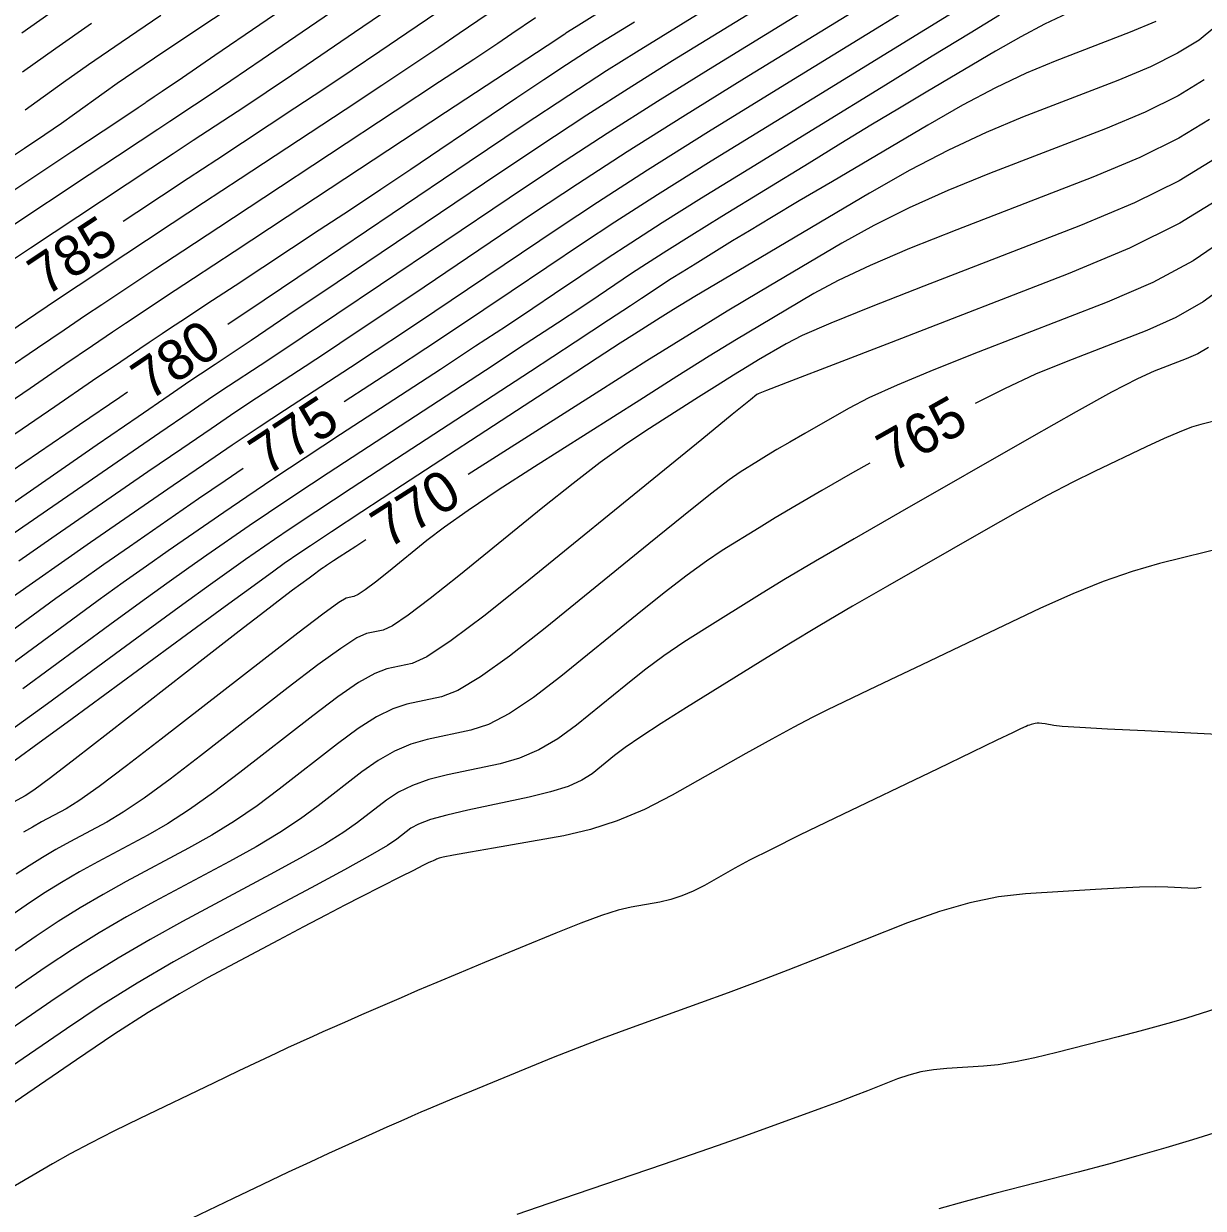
# Model space of a CAD drawing. Extents: x 2079879 to 2092887, y 778083 to 784051.
# Drawn here: x 2084644.1 to 2084725.9, y 781224.5 to 781306.6 of the extents above; entities that cross this region are included whole.
import ezdxf

# ---------------------------------------------------------------- set-up
doc = ezdxf.new("R2010")
doc.units = 0
doc.layers.add('DT_X_Contour_Major', color=7, linetype='Continuous')
doc.layers.add('DT_X_Contour_Minor', color=7, linetype='Continuous')

msp = doc.modelspace()

# ---------------------------------------------------------------- linework, layer by layer
at = {"layer": 'DT_X_Contour_Major'}
for points in [[(2084741.676, 781340.837), (2084739.539, 781339.138), (2084738.784, 781338.575), (2084737.437, 781337.615), (2084735.497, 781336.257), (2084732.963, 781334.501), (2084725.417, 781329.289), (2084722.475, 781327.287), (2084719.307, 781325.187), (2084715.915, 781322.99), (2084712.298, 781320.696), (2084702.351, 781314.45), (2084698.865, 781312.264), (2084695.864, 781310.388), (2084693.35, 781308.824), (2084691.322, 781307.571), (2084686.561, 781304.644), (2084684.498, 781303.346), (2084681.879, 781301.647), (2084678.705, 781299.547), (2084674.974, 781297.045), (2084664.286, 781289.839), (2084660.748, 781287.454), (2084658.242, 781285.766)], [(2084675.583, 781309.33), (2084670.653, 781305.96), (2084668.781, 781304.687), (2084666.863, 781303.395), (2084664.9, 781302.085), (2084662.89, 781300.756), (2084657.47, 781297.188), (2084655.498, 781295.889), (2084653.65, 781294.67), (2084651.925, 781293.53), (2084650.987, 781292.91)], [(2084709.118, 781307.766), (2084696.219, 781299.836), (2084691.754, 781297.078), (2084688.035, 781294.75), (2084685.06, 781292.852), (2084682.83, 781291.384), (2084677.876, 781288.044), (2084675.982, 781286.773), (2084674.013, 781285.463), (2084671.97, 781284.114), (2084669.854, 781282.726), (2084666.313, 781280.413)], [(2084653.584, 781307.181), (2084650.834, 781305.317), (2084648.586, 781303.768), (2084646.839, 781302.533), (2084644.183, 781300.621)], [(2084725.928, 781302.728), (2084724.124, 781301.616), (2084721.839, 781300.483), (2084719.073, 781299.33), (2084711.053, 781296.227), (2084708.156, 781295.053), (2084705.481, 781293.856), (2084703.028, 781292.636), (2084700.797, 781291.395), (2084695.143, 781288.054), (2084692.857, 781286.684), (2084690.242, 781285.08), (2084687.297, 781283.243), (2084684.022, 781281.171), (2084674.895, 781275.365)], [(2084727.617, 781288.617), (2084725.858, 781287.34), (2084723.966, 781286.25), (2084721.939, 781285.347), (2084716.357, 781283.187), (2084714.24, 781282.315), (2084712.077, 781281.32), (2084710.05, 781280.293)], [(2084651.276, 781281.073), (2084650.759, 781280.72), (2084647.95, 781278.804), (2084636.571, 781271.044)], [(2084659.302, 781275.786), (2084658.05, 781274.942), (2084656.208, 781273.68), (2084651.413, 781270.372), (2084649.647, 781269.145), (2084647.946, 781267.945), (2084646.308, 781266.773), (2084644.734, 781265.629), (2084640.624, 781262.613)], [(2084702.735, 781276.167), (2084701.539, 781275.482), (2084699.426, 781274.267), (2084697.643, 781273.229), (2084696.191, 781272.369), (2084695.069, 781271.685), (2084692.516, 781270.1), (2084691.43, 781269.378), (2084690.086, 781268.4), (2084688.484, 781267.166), (2084686.625, 781265.677), (2084681.322, 781261.365), (2084679.44, 781259.92), (2084677.773, 781258.818), (2084676.32, 781258.061), (2084675.081, 781257.649), (2084672.062, 781257.006), (2084670.93, 781256.685), (2084669.798, 781256.204), (2084668.665, 781255.562), (2084667.533, 781254.76), (2084664.512, 781252.406), (2084663.277, 781251.504), (2084661.838, 781250.562), (2084660.195, 781249.58), (2084658.347, 781248.559), (2084653.147, 781245.783), (2084651.216, 781244.719), (2084649.324, 781243.608), (2084647.47, 781242.451), (2084645.655, 781241.247), (2084640.867, 781237.976)], [(2084667.812, 781270.85), (2084667.107, 781270.395), (2084665.958, 781269.645), (2084665.574, 781269.394), (2084665.284, 781269.203), (2084665.088, 781269.074), (2084664.986, 781269.006), (2084664.839, 781268.904), (2084664.737, 781268.832), (2084664.541, 781268.689), (2084664.251, 781268.478), (2084663.867, 781268.196), (2084662.719, 781267.354), (2084662.022, 781266.828), (2084660.795, 781265.884), (2084659.036, 781264.521), (2084656.745, 781262.739), (2084649.929, 781257.428), (2084647.654, 781255.664), (2084645.94, 781254.357), (2084644.789, 781253.507), (2084644.198, 781253.114), (2084643.373, 781252.673)], [(2084725.724, 781246.75), (2084725.254, 781246.69), (2084723.402, 781246.781), (2084722.567, 781246.797), (2084721.452, 781246.776), (2084720.057, 781246.718), (2084718.381, 781246.623), (2084713.538, 781246.322), (2084711.665, 781246.111), (2084709.677, 781245.703), (2084707.575, 781245.1), (2084705.358, 781244.3), (2084699.294, 781241.905), (2084697.071, 781241.035), (2084694.949, 781240.22), (2084692.928, 781239.461), (2084691.008, 781238.757), (2084686.023, 781236.954), (2084684.196, 781236.284), (2084682.454, 781235.624), (2084680.796, 781234.976), (2084679.224, 781234.338), (2084675.143, 781232.652), (2084673.774, 781232.086), (2084672.73, 781231.652), (2084672.009, 781231.351), (2084671.612, 781231.183), (2084670.986, 781230.909), (2084670.638, 781230.756), (2084670.065, 781230.499), (2084669.267, 781230.14), (2084668.243, 781229.679), (2084665.213, 781228.311), (2084663.948, 781227.732), (2084662.426, 781227.021), (2084660.645, 781226.178), (2084658.607, 781225.204), (2084652.829, 781222.428)]]:
    msp.add_lwpolyline(points, dxfattribs=at)
at = {"layer": 'DT_X_Contour_Minor'}
for points in [[(2084669.907, 781312.997), (2084660.461, 781306.54), (2084657.347, 781304.412), (2084655.09, 781302.869), (2084653.688, 781301.912), (2084653.143, 781301.542), (2084652.832, 781301.334), (2084652.724, 781301.261), (2084652.632, 781301.199), (2084652.557, 781301.147), (2084652.499, 781301.106), (2084652.366, 781301.01), (2084652.024, 781300.782), (2084651.1, 781300.168), (2084649.593, 781299.169), (2084647.504, 781297.784), (2084641.154, 781293.578)], [(2084671.595, 781311.636), (2084663.383, 781306.022), (2084660.608, 781304.127), (2084658.441, 781302.652), (2084656.883, 781301.596), (2084655.933, 781300.961), (2084654.211, 781299.828), (2084653.378, 781299.279), (2084652.171, 781298.481), (2084650.59, 781297.435), (2084648.635, 781296.14), (2084642.923, 781292.356)], [(2084710.86, 781310.986), (2084696.559, 781302.195), (2084691.573, 781299.112), (2084687.34, 781296.457), (2084683.859, 781294.229), (2084681.131, 781292.43), (2084674.859, 781288.202), (2084672.587, 781286.675), (2084670.476, 781285.265), (2084668.524, 781283.971), (2084666.733, 781282.795), (2084662.168, 781279.813), (2084660.402, 781278.65), (2084658.528, 781277.396), (2084656.544, 781276.051), (2084654.452, 781274.615), (2084648.728, 781270.665), (2084646.702, 781269.261), (2084644.918, 781268.01), (2084643.374, 781266.913)], [(2084673.589, 781310.483), (2084667.018, 781305.991), (2084664.694, 781304.407), (2084662.652, 781303.023), (2084660.891, 781301.841), (2084659.411, 781300.859), (2084655.84, 781298.508), (2084654.438, 781297.584), (2084652.911, 781296.576), (2084651.257, 781295.482), (2084649.479, 781294.305), (2084644.567, 781291.051), (2084642.755, 781289.847)], [(2084705.975, 781310.132), (2084694.06, 781302.807), (2084689.794, 781300.164), (2084685.934, 781297.727), (2084682.48, 781295.498), (2084679.431, 781293.476), (2084671.842, 781288.359), (2084669.193, 781286.577), (2084666.939, 781285.067), (2084665.078, 781283.829), (2084663.611, 781282.863), (2084660.226, 781280.652), (2084658.803, 781279.711), (2084657.074, 781278.547), (2084655.039, 781277.16), (2084652.697, 781275.55), (2084646.043, 781270.959), (2084643.757, 781269.377)], [(2084701.091, 781309.278), (2084691.56, 781303.419), (2084688.016, 781301.216), (2084684.529, 781298.998), (2084681.102, 781296.767), (2084677.732, 781294.522), (2084668.825, 781288.517), (2084665.799, 781286.479), (2084663.401, 781284.868), (2084661.632, 781283.686), (2084660.49, 781282.932), (2084658.283, 781281.49), (2084657.204, 781280.772), (2084655.62, 781279.698), (2084653.533, 781278.269), (2084650.941, 781276.485), (2084643.358, 781271.252)], [(2084696.206, 781308.425), (2084689.061, 781304.032), (2084686.237, 781302.267), (2084683.124, 781300.269), (2084679.723, 781298.035), (2084676.033, 781295.567), (2084665.808, 781288.674), (2084662.405, 781286.381), (2084659.864, 781284.67), (2084658.185, 781283.544), (2084657.369, 781283), (2084656.341, 781282.329), (2084655.605, 781281.833), (2084654.167, 781280.85), (2084652.027, 781279.379), (2084649.186, 781277.42), (2084640.673, 781271.546)], [(2084659.657, 781308.566), (2084654.833, 781305.347), (2084653.154, 781304.221), (2084651.733, 781303.258), (2084650.572, 781302.458), (2084649.669, 781301.82), (2084647.608, 781300.335), (2084646.708, 781299.7), (2084645.554, 781298.909), (2084644.147, 781297.96), (2084642.487, 781296.854)], [(2084684.427, 781307.669), (2084682.38, 781306.384), (2084681.682, 781305.945), (2084681.596, 781305.892), (2084681.58, 781305.882), (2084681.569, 781305.875), (2084681.564, 781305.872), (2084681.557, 781305.867), (2084681.041, 781305.527), (2084673.326, 781300.448), (2084662.358, 781293.228), (2084658.679, 781290.805), (2084655.868, 781288.954), (2084653.926, 781287.674), (2084652.852, 781286.965), (2084651.147, 781285.835), (2084650.253, 781285.237), (2084648.852, 781284.289), (2084646.943, 781282.991), (2084644.525, 781281.344), (2084637.402, 781276.486)], [(2084677.576, 781308.177), (2084674.288, 781305.929), (2084672.868, 781304.967), (2084671.075, 781303.767), (2084668.908, 781302.329), (2084666.369, 781300.654), (2084659.099, 781295.868), (2084656.558, 781294.195), (2084654.389, 781292.765), (2084652.592, 781291.578), (2084651.165, 781290.635), (2084647.857, 781288.443), (2084646.504, 781287.542), (2084644.927, 781286.482), (2084643.126, 781285.262)], [(2084646.452, 781307.711), (2084643.969, 781305.958)], [(2084686.437, 781306.717), (2084684.062, 781305.257), (2084683.032, 781304.609), (2084681.725, 781303.761), (2084680.141, 781302.713), (2084678.28, 781301.465), (2084672.946, 781297.869), (2084670.923, 781296.509), (2084668.853, 781295.127), (2084666.737, 781293.722), (2084664.574, 781292.294), (2084658.745, 781288.457), (2084656.79, 781287.17), (2084655.297, 781286.186), (2084654.265, 781285.506), (2084653.696, 781285.13), (2084652.792, 781284.531), (2084652.128, 781284.084), (2084650.814, 781283.192), (2084648.851, 781281.856), (2084646.238, 781280.074), (2084638.403, 781274.731)], [(2084711.742, 781307.2), (2084709.71, 781305.967), (2084707.07, 781304.355), (2084703.824, 781302.362), (2084694.356, 781296.542), (2084691.079, 781294.517), (2084688.349, 781292.808), (2084686.166, 781291.415), (2084684.529, 781290.338), (2084680.893, 781287.887), (2084679.376, 781286.871), (2084677.55, 781285.661), (2084675.417, 781284.256), (2084672.975, 781282.658), (2084666.053, 781278.136), (2084663.601, 781276.528), (2084661.435, 781275.093), (2084659.556, 781273.832), (2084657.963, 781272.745), (2084654.098, 781270.078), (2084652.593, 781269.029), (2084650.974, 781267.881), (2084649.242, 781266.634), (2084647.397, 781265.288), (2084642.327, 781261.569)], [(2084679.57, 781307.024), (2084677.923, 781305.898), (2084676.954, 781305.247), (2084675.286, 781304.139), (2084672.917, 781302.574), (2084669.847, 781300.551), (2084660.728, 781294.548), (2084657.619, 781292.5), (2084655.129, 781290.86), (2084653.259, 781289.626), (2084652.009, 781288.8), (2084649.502, 781287.139), (2084648.379, 781286.389), (2084646.89, 781285.385), (2084645.034, 781284.127), (2084642.813, 781282.614)], [(2084722.574, 781306.775), (2084720.786, 781306.03), (2084715.605, 781304.026), (2084713.595, 781303.185), (2084711.45, 781302.165), (2084709.172, 781300.968), (2084706.76, 781299.592), (2084700.148, 781295.685), (2084697.856, 781294.328), (2084695.94, 781293.188), (2084694.4, 781292.263), (2084693.235, 781291.554), (2084690.631, 781289.953), (2084689.729, 781289.396), (2084688.978, 781288.926), (2084688.378, 781288.543), (2084687.927, 781288.247), (2084686.927, 781287.572), (2084686.164, 781287.067), (2084684.625, 781286.057), (2084682.309, 781284.541), (2084679.218, 781282.521), (2084669.938, 781276.46), (2084666.8, 781274.406), (2084664.343, 781272.791), (2084662.568, 781271.614), (2084661.474, 781270.876), (2084659.469, 781269.491), (2084658.483, 781268.797), (2084657.03, 781267.751), (2084655.11, 781266.355), (2084652.722, 781264.608), (2084645.733, 781259.48), (2084643.241, 781257.671)], [(2084716.421, 781307.314), (2084714.864, 781306.574), (2084713.21, 781305.704), (2084711.458, 781304.705), (2084706.657, 781301.869), (2084704.799, 781300.764), (2084702.825, 781299.577), (2084700.735, 781298.309), (2084698.53, 781296.958), (2084692.494, 781293.248), (2084690.404, 781291.957), (2084688.664, 781290.867), (2084687.272, 781289.979), (2084686.228, 781289.293), (2084683.91, 781287.73), (2084682.77, 781286.969), (2084681.087, 781285.859), (2084678.863, 781284.399), (2084676.096, 781282.589), (2084667.996, 781277.298), (2084665.2, 781275.467), (2084662.889, 781273.942), (2084661.062, 781272.723), (2084659.719, 781271.81), (2084656.783, 781269.785), (2084655.538, 781268.913), (2084654.002, 781267.816), (2084652.176, 781266.494), (2084650.06, 781264.948), (2084644.03, 781260.525)], [(2084726.66, 781306.375), (2084725.572, 781305.477), (2084724.087, 781304.562), (2084722.206, 781303.629), (2084719.929, 781302.68), (2084713.329, 781300.127), (2084710.81, 781299.08), (2084708.203, 781297.855), (2084705.509, 781296.453), (2084702.728, 781294.873), (2084695.194, 781290.422), (2084692.639, 781288.908), (2084690.623, 781287.705), (2084689.146, 781286.814), (2084688.208, 781286.233), (2084686.427, 781285.1), (2084685.447, 781284.47), (2084683.846, 781283.431), (2084681.621, 781281.982), (2084678.775, 781280.124), (2084670.353, 781274.623), (2084667.54, 781272.784), (2084665.415, 781271.39), (2084663.978, 781270.442), (2084663.23, 781269.941), (2084662.154, 781269.198), (2084661.428, 781268.681), (2084660.058, 781267.687), (2084658.043, 781266.216), (2084655.385, 781264.267), (2084647.436, 781258.436), (2084644.817, 781256.516), (2084642.922, 781255.129)], [(2084648.799, 781306.618), (2084646.317, 781304.889), (2084644.01, 781303.247)], [(2084726.284, 781299.979), (2084724.162, 781298.671), (2084721.472, 781297.338), (2084718.216, 781295.98), (2084708.777, 781292.328), (2084705.503, 781291.026), (2084702.76, 781289.856), (2084700.547, 781288.82), (2084698.866, 781287.917), (2084695.091, 781285.686), (2084693.511, 781284.737), (2084691.601, 781283.562), (2084689.362, 781282.162), (2084686.794, 781280.536), (2084679.507, 781275.9), (2084676.991, 781274.277), (2084674.907, 781272.885), (2084673.256, 781271.724), (2084672.038, 781270.794), (2084669.367, 781268.622), (2084668.466, 781267.904), (2084667.766, 781267.379), (2084667.268, 781267.047), (2084666.97, 781266.909), (2084666.445, 781266.797), (2084665.94, 781266.501), (2084664.819, 781265.697), (2084663.081, 781264.385), (2084660.727, 781262.564), (2084653.628, 781257.032), (2084651.218, 781255.175), (2084649.315, 781253.751), (2084647.919, 781252.76), (2084647.028, 781252.203), (2084645.328, 781251.295), (2084644.697, 781250.947), (2084644.078, 781250.584)], [(2084726.641, 781297.23), (2084724.199, 781295.725), (2084721.105, 781294.192), (2084717.359, 781292.63), (2084706.501, 781288.429), (2084702.849, 781286.998), (2084700.038, 781285.856), (2084698.066, 781285.003), (2084696.935, 781284.438), (2084695.039, 781283.318), (2084694.245, 781282.841), (2084693.286, 781282.251), (2084692.162, 781281.548), (2084690.872, 781280.732), (2084687.212, 781278.403), (2084685.737, 781277.416), (2084684.058, 781276.203), (2084682.174, 781274.761), (2084680.085, 781273.093), (2084674.242, 781268.341), (2084672.27, 781266.77), (2084670.739, 781265.622), (2084669.649, 781264.897), (2084668.998, 781264.594), (2084667.849, 781264.349), (2084667.188, 781264.047), (2084666.064, 781263.324), (2084664.477, 781262.179), (2084662.428, 781260.613), (2084656.349, 781255.876), (2084654.233, 781254.257), (2084652.446, 781252.953), (2084650.988, 781251.965), (2084649.858, 781251.292), (2084647.283, 781249.917), (2084646.326, 781249.39), (2084645.389, 781248.84), (2084644.472, 781248.267), (2084643.573, 781247.671)], [(2084726.997, 781294.482), (2084724.236, 781292.78), (2084720.738, 781291.046), (2084716.503, 781289.28), (2084704.225, 781284.53), (2084700.196, 781282.971), (2084697.316, 781281.857), (2084695.585, 781281.186), (2084695.004, 781280.96), (2084694.987, 781280.95), (2084694.98, 781280.946), (2084694.972, 781280.941), (2084694.962, 781280.935), (2084694.918, 781280.906), (2084694.484, 781280.556), (2084693.209, 781279.52), (2084691.091, 781277.799), (2084688.132, 781275.392), (2084679.116, 781268.06), (2084676.075, 781265.637), (2084673.712, 781263.865), (2084672.029, 781262.746), (2084671.025, 781262.279), (2084669.254, 781261.902), (2084668.435, 781261.593), (2084667.308, 781260.95), (2084665.873, 781259.973), (2084664.13, 781258.662), (2084659.07, 781254.719), (2084657.248, 781253.339), (2084655.577, 781252.156), (2084654.057, 781251.17), (2084652.687, 781250.381), (2084649.237, 781248.539), (2084647.956, 781247.833), (2084646.701, 781247.096), (2084645.471, 781246.328), (2084644.267, 781245.53), (2084641.09, 781243.359)], [(2084727.576, 781291.819), (2084725.163, 781290.178), (2084722.373, 781288.674), (2084719.205, 781287.307), (2084710.253, 781283.844), (2084707.174, 781282.627), (2084704.651, 781281.571), (2084702.684, 781280.679), (2084701.272, 781279.949), (2084698.248, 781278.218), (2084697.196, 781277.613), (2084696.309, 781277.096), (2084695.586, 781276.668), (2084695.028, 781276.328), (2084693.757, 781275.539), (2084693.004, 781275.006), (2084691.696, 781274), (2084689.834, 781272.52), (2084687.418, 781270.567), (2084680.236, 781264.726), (2084677.767, 781262.786), (2084675.747, 781261.345), (2084674.176, 781260.405), (2084673.053, 781259.964), (2084670.658, 781259.454), (2084669.682, 781259.139), (2084668.553, 781258.577), (2084667.269, 781257.768), (2084665.831, 781256.711), (2084661.791, 781253.563), (2084660.263, 781252.421), (2084658.707, 781251.359), (2084657.126, 781250.375), (2084655.517, 781249.47), (2084651.192, 781247.161), (2084649.586, 781246.276), (2084648.012, 781245.352), (2084646.471, 781244.39), (2084644.961, 781243.389), (2084640.978, 781240.668)], [(2084726.227, 781284.177), (2084725.477, 781283.744), (2084724.673, 781283.386), (2084722.46, 781282.53), (2084721.306, 781282.004), (2084719.504, 781281.069), (2084717.054, 781279.724), (2084713.956, 781277.97), (2084704.83, 781272.746), (2084701.656, 781270.921), (2084698.977, 781269.362), (2084696.795, 781268.069), (2084695.109, 781267.043), (2084691.275, 781264.661), (2084689.856, 781263.75), (2084688.476, 781262.8), (2084687.134, 781261.812), (2084685.831, 781260.787), (2084682.408, 781258.003), (2084681.113, 781257.053), (2084679.799, 781256.292), (2084678.464, 781255.718), (2084677.108, 781255.334), (2084673.466, 781254.559), (2084672.177, 781254.231), (2084671.042, 781253.831), (2084670.061, 781253.356), (2084669.234, 781252.808), (2084667.233, 781251.249), (2084666.292, 781250.586), (2084664.969, 781249.764), (2084663.263, 781248.785), (2084661.176, 781247.648), (2084655.101, 781244.405), (2084652.846, 781243.161), (2084650.635, 781241.864), (2084648.47, 781240.512), (2084646.349, 781239.106), (2084640.755, 781235.284)], [(2084727.144, 781279.205), (2084725.692, 781278.841), (2084725.048, 781278.642), (2084724.202, 781278.317), (2084723.157, 781277.866), (2084721.91, 781277.29), (2084718.318, 781275.585), (2084716.828, 781274.847), (2084715.05, 781273.911), (2084712.986, 781272.779), (2084710.634, 781271.449), (2084703.979, 781267.64), (2084701.555, 781266.241), (2084699.276, 781264.902), (2084697.141, 781263.621), (2084695.15, 781262.4), (2084690.034, 781259.223), (2084688.283, 781258.121), (2084686.866, 781257.2), (2084685.785, 781256.459), (2084685.038, 781255.897), (2084683.493, 781254.641), (2084682.787, 781254.187), (2084681.825, 781253.765), (2084680.608, 781253.375), (2084679.136, 781253.019), (2084674.87, 781252.111), (2084673.425, 781251.777), (2084672.287, 781251.457), (2084671.457, 781251.15), (2084670.935, 781250.857), (2084669.954, 781250.093), (2084669.307, 781249.668), (2084668.099, 781248.967), (2084666.332, 781247.99), (2084664.006, 781246.737), (2084657.056, 781243.026), (2084654.475, 781241.604), (2084651.946, 781240.12), (2084649.469, 781238.573), (2084647.043, 781236.965), (2084640.643, 781232.592)], [(2084727.704, 781270.418), (2084722.823, 781269.196), (2084720.935, 781268.659), (2084718.932, 781267.964), (2084716.813, 781267.112), (2084714.579, 781266.103), (2084708.467, 781263.201), (2084706.351, 781262.196), (2084704.588, 781261.357), (2084703.178, 781260.685), (2084702.12, 781260.178), (2084699.769, 781259.048), (2084698.757, 781258.542), (2084697.486, 781257.871), (2084695.953, 781257.037), (2084694.161, 781256.038), (2084689.034, 781253.155), (2084687.123, 781252.168), (2084685.237, 781251.371), (2084683.374, 781250.764), (2084681.536, 781250.346), (2084676.668, 781249.485), (2084675.061, 781249.199), (2084673.895, 781248.987), (2084673.168, 781248.848), (2084672.88, 781248.783), (2084672.699, 781248.708), (2084672.634, 781248.681), (2084672.574, 781248.656), (2084672.52, 781248.633), (2084672.471, 781248.612), (2084672.348, 781248.558), (2084672.18, 781248.476), (2084671.767, 781248.27), (2084671.11, 781247.94), (2084670.209, 781247.486), (2084667.481, 781246.11), (2084666.355, 781245.535), (2084665.024, 781244.844), (2084663.488, 781244.035), (2084661.747, 781243.109), (2084656.83, 781240.484), (2084654.878, 781239.392), (2084652.713, 781238.085), (2084650.332, 781236.562), (2084647.737, 781234.823), (2084640.532, 781229.901)], [(2084729.567, 781257.219), (2084721.8, 781257.603), (2084719.222, 781257.734), (2084717.315, 781257.839), (2084716.078, 781257.919), (2084715.512, 781257.974), (2084714.896, 781258.085), (2084714.68, 781258.118), (2084714.496, 781258.134), (2084714.342, 781258.133), (2084714.22, 781258.115), (2084713.935, 781258.043), (2084713.825, 781258.012), (2084713.708, 781257.972), (2084713.584, 781257.922), (2084713.454, 781257.863), (2084713.097, 781257.693), (2084712.645, 781257.477), (2084711.556, 781256.954), (2084709.831, 781256.125), (2084707.468, 781254.989), (2084700.32, 781251.553), (2084697.876, 781250.37), (2084695.905, 781249.398), (2084694.406, 781248.638), (2084693.38, 781248.088), (2084691.274, 781246.904), (2084690.49, 781246.499), (2084689.715, 781246.171), (2084688.95, 781245.922), (2084688.195, 781245.75), (2084686.195, 781245.397), (2084685.307, 781245.185), (2084684.142, 781244.814), (2084682.701, 781244.285), (2084680.983, 781243.598), (2084676.034, 781241.553), (2084674.281, 781240.826), (2084672.735, 781240.178), (2084671.394, 781239.61), (2084670.26, 781239.12), (2084667.509, 781237.921), (2084666.525, 781237.49), (2084665.634, 781237.098), (2084664.836, 781236.744), (2084664.133, 781236.428), (2084662.38, 781235.637), (2084661.566, 781235.262), (2084660.439, 781234.732), (2084658.997, 781234.047), (2084657.242, 781233.206), (2084652.144, 781230.756), (2084650.331, 781229.87), (2084648.718, 781229.05), (2084647.305, 781228.296), (2084646.09, 781227.609), (2084643.117, 781225.863)], [(2084726.74, 781238.339), (2084724.694, 781237.703), (2084723.823, 781237.443), (2084722.745, 781237.14), (2084721.459, 781236.794), (2084719.966, 781236.405), (2084715.709, 781235.31), (2084714.193, 781234.943), (2084712.84, 781234.664), (2084711.649, 781234.474), (2084710.621, 781234.371), (2084708.094, 781234.213), (2084707.168, 781234.124), (2084706.286, 781233.972), (2084705.449, 781233.76), (2084704.655, 781233.485), (2084702.596, 781232.672), (2084701.726, 781232.335), (2084700.66, 781231.934), (2084699.398, 781231.468), (2084697.941, 781230.938), (2084693.792, 781229.438), (2084692.158, 781228.853), (2084690.366, 781228.224), (2084688.417, 781227.551), (2084686.311, 781226.833), (2084680.483, 781224.861), (2084678.274, 781224.085)], [(2084729.913, 781230.763), (2084725.11, 781229.269), (2084723.263, 781228.71), (2084721.326, 781228.151), (2084719.297, 781227.593), (2084717.179, 781227.036), (2084711.408, 781225.552), (2084709.357, 781225.006), (2084707.53, 781224.482)]]:
    msp.add_lwpolyline(points, dxfattribs=at)

# ---------------------------------------------------------------- texts
at = {"layer": 'DT_X_Contour_Major'}
for s, rotation, p in [('785', 33.57543, (2084645.624, 781287.675)), ('780', 33.96993, (2084652.808, 781280.437)), ('775', 33.42499, (2084660.948, 781275.214)), ('765', 29.42772, (2084704.293, 781275.468)), ('770', 32.51595, (2084669.353, 781270.175))]:
    msp.add_text(s, height=2.8, rotation=rotation, dxfattribs=at).set_placement(p)

doc.saveas('drawing.dxf')
